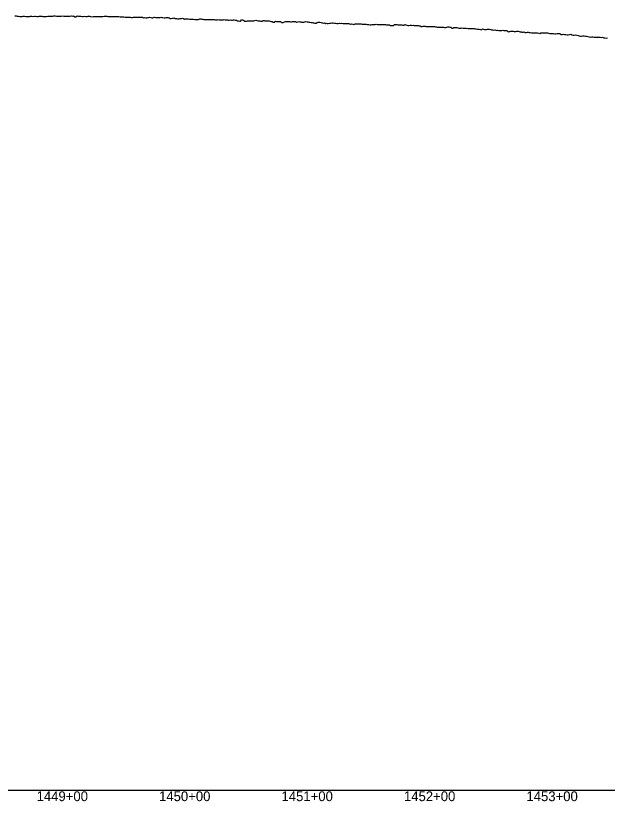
# Model space of a CAD drawing. Extents: x -3793 to 50787, y -1075 to 6138.
# Drawn here: x 32241 to 32724, y 991 to 1633 of the extents above; entities that cross this region are included whole.
import ezdxf

# ---------------------------------------------------------------- set-up
doc = ezdxf.new("R2010")
doc.units = 0
for name, color, linetype in [('RD_DDB_Profile_EX', 7, 'Continuous'), ('RD_DDB_StaTX', 7, 'Continuous'), ('RD_GPK_Profile_Cell', 7, 'Continuous')]:
    doc.layers.add(name, color=color, linetype=linetype)

msp = doc.modelspace()

# ---------------------------------------------------------------- linework, layer by layer
at = {"layer": 'RD_DDB_Profile_EX'}
for points in [[(32240.641397, 1632.72574), (32241.599053, 1632.53108), (32242.558609, 1632.480035), (32243.518571, 1632.288225), (32244.677049, 1632.131755), (32245.636323, 1631.98429), (32246.597516, 1631.98092), (32247.560636, 1632.266615), (32248.525687, 1632.26352), (32249.66571, 1632.157575), (32250.629589, 1632.106235), (32251.595418, 1632.15152), (32252.563204, 1632.196895), (32253.531405, 1632.34229), (32254.656743, 1632.439955), (32255.624286, 1632.194595), (32256.593804, 1632.24002), (32257.565305, 1632.28554), (32258.538795, 1632.136565), (32259.644937, 1632.129925), (32260.607504, 1632.224305), (32261.581846, 1632.27013), (32262.558202, 1632.21836), (32263.536578, 1632.21538), (32264.62576, 1632.213695), (32265.601917, 1632.16186), (32266.58011, 1632.1589), (32267.560345, 1632.254005), (32268.542628, 1632.300225), (32269.613406, 1632.303745), (32270.59455, 1632.300535), (32271.577764, 1632.346555), (32272.563053, 1632.58983), (32273.550424, 1632.537575), (32274.603564, 1632.285965), (32275.588701, 1632.283135), (32276.575938, 1632.32973), (32277.565279, 1632.32694), (32278.556732, 1632.373685), (32279.590678, 1632.520245), (32280.581013, 1632.36863), (32281.573481, 1632.4155), (32282.568089, 1632.46247), (32283.564845, 1632.40992), (32284.577491, 1632.30854), (32285.574884, 1632.30873), (32286.571559, 1632.554935), (32287.569303, 1632.458675), (32288.562945, 1632.51533), (32289.587271, 1631.920555), (32290.584363, 1631.92794), (32291.576172, 1632.57517), (32292.565584, 1632.479285), (32293.550939, 1632.436), (32294.608558, 1632.3379), (32295.597275, 1632.19639), (32296.580765, 1632.19959), (32297.561347, 1632.30374), (32298.538989, 1632.062265), (32299.632567, 1632.125265), (32300.610129, 1632.27509), (32301.585338, 1632.32722), (32302.557671, 1631.94539), (32303.527095, 1631.900735), (32304.653631, 1632.1362), (32305.622926, 1632.04265), (32306.590464, 1632.04886), (32307.554013, 1632.100185), (32308.515256, 1632.00712), (32309.674601, 1631.99166), (32310.635665, 1631.99425), (32311.594992, 1632.094865), (32312.550373, 1632.14506), (32313.501875, 1632.292595), (32314.695477, 1632.247825), (32315.648348, 1632.345095), (32316.599501, 1632.15975), (32317.54675, 1632.02013), (32318.490162, 1632.07229), (32319.716259, 1632.08406), (32320.662596, 1632.089215), (32321.603991, 1632.044865), (32322.543145, 1632.1414), (32323.478504, 1632.09958)], [(32323.478504, 1632.09958), (32324.412152, 1631.961905), (32324.736948, 1631.956355), (32325.675149, 1632.054825), (32326.608462, 1631.82448), (32327.539055, 1631.73703), (32328.4669, 1631.73995), (32329.392548, 1631.6965), (32329.757545, 1631.697665), (32330.687647, 1631.610995), (32331.612914, 1631.66024), (32332.535491, 1631.62003), (32333.455348, 1631.531045), (32334.370483, 1631.44536), (32334.780657, 1631.43447), (32335.70009, 1631.39174), (32336.617881, 1631.397865), (32337.531943, 1631.446665), (32338.44385, 1631.586595), (32339.356138, 1631.541125), (32339.795882, 1631.546965), (32340.709373, 1631.45892), (32341.62017, 1631.50461), (32342.530857, 1631.59583), (32343.441434, 1631.59598), (32344.349365, 1631.59894), (32344.80337, 1631.60953), (32345.712441, 1631.06436), (32346.621402, 1631.15543), (32347.530253, 1631.0193), (32348.437476, 1630.977695), (32349.345081, 1631.340945), (32349.808317, 1631.319455), (32350.715536, 1631.41032), (32351.622643, 1631.319775), (32352.529147, 1631.05115), (32353.435006, 1631.006035), (32354.340755, 1631.549685), (32354.813307, 1631.57488), (32355.718655, 1631.30349), (32356.624429, 1631.21656), (32357.528526, 1631.26194), (32358.432512, 1631.35252), (32359.336388, 1631.39789), (32359.818339, 1631.41902), (32360.723372, 1631.287275), (32361.625689, 1631.24236), (32362.527896, 1630.971915), (32363.429992, 1631.01723), (32364.329423, 1631.156445), (32364.826026, 1631.153625), (32365.726548, 1631.19884), (32366.626959, 1631.018975), (32367.527258, 1630.47905), (32368.427447, 1630.569305), (32369.324963, 1630.61883), (32369.831153, 1630.65184), (32370.729751, 1630.92161), (32371.628237, 1630.427745), (32372.526612, 1630.33818), (32373.423343, 1630.298555), (32374.32046, 1630.298825), (32374.836325, 1630.28635), (32375.732981, 1630.331435), (32376.629525, 1630.42134), (32377.525459, 1630.69491), (32378.420742, 1630.33704), (32379.315913, 1630.02398), (32379.841543, 1630.04301), (32380.736239, 1630.088025), (32381.631363, 1630.13829), (32382.524794, 1630.093905), (32383.418113, 1630.00486), (32384.311321, 1629.871165), (32384.846807, 1629.869315), (32385.74111, 1629.83057), (32386.632671, 1629.87544), (32387.52412, 1629.608325), (32388.415458, 1629.69777), (32389.304102, 1629.61478), (32389.854754, 1629.618585), (32390.744428, 1629.66337), (32391.633989, 1630.108395), (32392.523438, 1630.06421), (32393.411231, 1629.98099), (32394.299412, 1629.80364), (32394.860119, 1629.7624), (32395.747774, 1629.49644), (32396.63586, 1629.502285), (32397.522244, 1629.546895), (32398.408516, 1629.591505), (32399.292088, 1629.55296), (32399.868176, 1629.54517), (32400.743883, 1629.5454), (32401.62835, 1629.501475), (32402.512213, 1629.551365), (32403.395409, 1629.595815), (32404.278493, 1629.28701), (32404.864792, 1629.27336), (32405.748917, 1629.27922), (32406.630275, 1629.676065)], [(32406.630275, 1629.676065), (32407.511521, 1629.45605), (32408.392654, 1629.456335), (32409.271092, 1629.329955), (32409.872991, 1629.267505), (32410.75238, 1629.22381), (32411.631656, 1629.53178), (32412.510327, 1629.49274), (32413.388329, 1629.44909), (32414.266219, 1629.229865), (32414.878587, 1629.16596), (32415.757482, 1629.170615), (32416.633605, 1629.34605), (32417.509615, 1629.214885), (32418.383971, 1629.21947), (32419.258707, 1629.35092), (32419.886901, 1629.297385), (32420.761011, 1629.079105), (32421.635566, 1628.952395), (32422.5084, 1628.647155), (32423.38112, 1628.560125), (32424.253728, 1628.25495), (32424.892606, 1628.252395), (32425.766184, 1629.38955), (32426.636982, 1629.389745), (32427.507667, 1629.128755), (32428.376695, 1628.219875), (32429.246104, 1628.30709), (32429.901037, 1628.23871), (32430.76978, 1628.542935), (32431.638968, 1628.63384), (32432.50643, 1628.590675), (32433.37378, 1628.590885), (32434.238422, 1628.59498), (32434.909528, 1628.571235), (32435.775024, 1628.57143), (32436.640408, 1628.74468), (32437.505182, 1629.05079), (32438.369286, 1628.83494), (32439.233276, 1628.662315), (32439.915407, 1628.610555), (32440.77869, 1628.481265), (32441.642418, 1628.35547), (32442.504418, 1628.269465), (32443.366304, 1628.82987), (32444.225477, 1628.70381), (32444.924019, 1628.601315), (32445.784008, 1628.515455), (32446.643882, 1628.60156), (32447.503147, 1628.64688), (32448.364846, 1628.470425), (32449.228057, 1628.166525), (32449.921942, 1628.106275), (32450.781227, 1628.01787), (32451.641964, 1627.537935), (32452.506374, 1627.53503), (32453.372825, 1628.22486), (32454.244002, 1628.04693), (32454.906101, 1628.062185), (32455.771721, 1628.016345), (32456.63941, 1628.10078), (32457.50969, 1628.09586), (32458.38264, 1627.090185), (32459.257685, 1627.08657), (32459.892586, 1627.0704), (32460.761915, 1627.71931), (32461.636181, 1627.97936), (32462.51257, 1628.064655), (32463.391089, 1628.062365), (32464.274542, 1627.8816), (32464.875798, 1627.889555), (32465.753546, 1627.622835), (32466.633452, 1627.61991), (32467.516065, 1627.879), (32468.401468, 1628.00911), (32469.289059, 1628.00665), (32469.86142, 1627.962485), (32470.743137, 1627.425835), (32471.630014, 1627.64525), (32472.51911, 1627.86521), (32473.412168, 1627.81614), (32474.306913, 1627.59064), (32474.843599, 1627.576175), (32475.734217, 1627.48446), (32476.617492, 1627.56888), (32477.513837, 1627.611335), (32478.412464, 1627.87841), (32479.313381, 1627.60665), (32479.819257, 1627.592895), (32480.714121, 1627.45325), (32481.614398, 1627.45087), (32482.516998, 1627.31301), (32483.423735, 1627.081325), (32484.332252, 1627.033115), (32484.800228, 1627.03481), (32485.704532, 1626.62358), (32486.610523, 1626.61637), (32487.520827, 1627.25048), (32488.433521, 1627.43021), (32489.351743, 1627.425145), (32489.780549, 1627.374795)], [(32489.780549, 1627.374795), (32490.692663, 1627.28152), (32491.607204, 1626.95891), (32492.524776, 1626.770355), (32493.445496, 1626.85979), (32494.36868, 1626.488795), (32494.763522, 1626.50606), (32495.682406, 1626.45673), (32496.603059, 1626.449935), (32497.52824, 1626.770645), (32498.455931, 1626.76776), (32499.389426, 1626.808275), (32499.74253, 1626.7705), (32500.669737, 1626.81485), (32501.600222, 1626.721935), (32502.529942, 1626.677975), (32503.456829, 1626.355905), (32504.38419, 1626.35606), (32504.748553, 1626.360915), (32505.67765, 1626.64167), (32506.603902, 1626.45956), (32507.527324, 1626.508655), (32508.447927, 1626.46548), (32509.365725, 1626.42244), (32509.76833, 1626.395475), (32510.687673, 1626.395605), (32511.607593, 1626.352255), (32512.524698, 1626.354855), (32513.438999, 1626.357445), (32514.350511, 1625.81193), (32514.784729, 1625.8092), (32515.699772, 1625.99485), (32516.61201, 1625.770415), (32517.522063, 1625.67959), (32518.430044, 1626.092), (32519.335251, 1626.185635), (32519.801175, 1626.168355), (32520.709841, 1626.12561), (32521.615716, 1626.037815), (32522.518815, 1625.9954), (32523.419149, 1626.043205), (32524.319946, 1625.81813), (32524.817669, 1625.829805), (32525.719938, 1625.83299), (32526.619433, 1625.791305), (32527.516166, 1625.83934), (32528.410151, 1625.618855), (32529.3014, 1625.488365), (32529.837532, 1625.479825), (32530.732072, 1625.3943), (32531.62316, 1625.34994), (32532.51351, 1625.620575), (32533.401126, 1625.66833), (32534.286023, 1625.671595), (32534.854102, 1625.673695), (32535.742215, 1625.765435), (32536.627594, 1625.68024), (32537.510844, 1625.59209), (32538.392074, 1625.595485), (32539.270599, 1625.510825), (32539.870719, 1625.48311), (32540.752387, 1625.4863), (32541.631337, 1625.44564), (32542.507581, 1625.492655), (32543.38113, 1625.539525), (32544.255131, 1625.233765), (32544.887385, 1625.191925), (32545.762589, 1625.238615), (32546.63509, 1625.285165), (32547.504901, 1624.592885), (32548.372035, 1624.640285), (32549.236502, 1624.687535), (32549.907334, 1624.63667), (32550.774775, 1625.41761), (32551.638853, 1625.460915), (32552.502213, 1625.50611), (32553.362911, 1625.29279), (32554.22096, 1625.16612), (32554.924077, 1625.196415), (32555.785023, 1625.19921), (32556.642627, 1625.285095), (32557.500095, 1625.070885), (32558.357428, 1625.113905), (32559.214626, 1625.41409), (32559.93125, 1625.337025), (32560.789487, 1624.911355), (32561.644373, 1624.78327), (32562.499122, 1624.61247), (32563.353736, 1625.039915), (32564.208214, 1624.86912), (32564.938506, 1624.84924), (32565.794001, 1624.93672), (32566.646136, 1624.681235), (32567.498134, 1624.68136), (32568.349997, 1624.80927), (32569.201723, 1624.7668), (32569.945845, 1624.739025), (32570.798565, 1624.528855), (32571.647917, 1624.52898), (32572.497131, 1624.01963), (32573.346209, 1623.93489)], [(32573.346209, 1623.93489), (32574.195151, 1624.104865), (32574.953269, 1624.06202), (32575.803182, 1624.1071), (32576.649716, 1623.93796), (32577.496113, 1623.93811), (32578.342373, 1623.980575), (32579.188496, 1623.896105), (32579.96078, 1623.883365), (32580.80785, 1623.928445), (32581.651533, 1624.01294), (32582.486649, 1623.970875), (32583.330072, 1623.928845), (32584.173357, 1623.760325), (32584.959924, 1623.73953), (32585.804144, 1623.49022), (32586.644955, 1623.448355), (32587.485628, 1623.23838), (32588.326164, 1623.280595), (32589.166562, 1623.44887), (32589.967642, 1623.427975), (32590.806956, 1623.38618), (32591.646839, 1623.18), (32592.484591, 1623.222065), (32593.322204, 1623.389765), (32594.15968, 1623.599315), (32594.975452, 1623.52845), (32595.811813, 1623.444955), (32596.648744, 1623.280445), (32597.483537, 1622.48761), (32598.318193, 1622.48781), (32599.152709, 1623.030485), (32599.983356, 1622.96689), (32600.816726, 1622.96702), (32601.650668, 1622.96961), (32602.482467, 1622.761815), (32603.314128, 1622.55405), (32604.145649, 1622.55422), (32604.991356, 1622.515095), (32605.821698, 1622.722775), (32606.652613, 1622.683935), (32607.481381, 1622.642635), (32608.310009, 1622.642775), (32609.144855, 1622.38838), (32609.992791, 1622.44269), (32610.820647, 1622.397915), (32611.650983, 1622.353005), (32612.484408, 1622.346055), (32613.321071, 1622.30086), (32614.160257, 1622.297395), (32614.977258, 1622.21915), (32615.811265, 1622.258145), (32616.647071, 1622.12638), (32617.487534, 1621.871025), (32618.330572, 1621.86761), (32619.179556, 1621.8183), (32619.957636, 1621.767215), (32620.799389, 1621.42612), (32621.64376, 1621.29555), (32622.491392, 1621.88203), (32623.342441, 1621.70903), (32624.196154, 1621.4929), (32624.94084, 1621.444005), (32625.787025, 1621.394975), (32626.639531, 1621.733615), (32627.494746, 1621.730965), (32628.354778, 1621.63962), (32629.216907, 1621.37878), (32629.919683, 1621.31821), (32630.77642, 1621.05751), (32631.635116, 1621.051205), (32632.498882, 1621.09135), (32633.356817, 1620.828525), (32634.229857, 1620.777975), (32634.888915, 1620.800835), (32635.754342, 1620.710145), (32636.622626, 1620.7062), (32637.494452, 1620.74172), (32638.370024, 1620.737805), (32639.248506, 1620.821515), (32639.869797, 1620.712185), (32640.742738, 1620.62202), (32641.617739, 1620.52858), (32642.498136, 1620.56982), (32643.381511, 1619.596125), (32644.271748, 1619.808475), (32644.845816, 1619.851785), (32645.728157, 1620.0687), (32646.613532, 1620.153205), (32647.50267, 1620.144695), (32648.39579, 1619.872825), (32649.292002, 1619.86819), (32649.824987, 1619.801675), (32650.712915, 1619.973325), (32651.60821, 1620.05971), (32652.506657, 1619.83165), (32653.410696, 1619.643625), (32654.317196, 1619.4588), (32654.798922, 1619.38877), (32655.699643, 1619.385615), (32656.602632, 1619.560725)], [(32656.602632, 1619.560725), (32657.510799, 1619.01605), (32658.421269, 1619.012205), (32659.335023, 1619.28175), (32659.780647, 1619.265685), (32660.688546, 1618.98898), (32661.600753, 1618.89798), (32662.513546, 1618.80286), (32663.429683, 1618.798925), (32664.349184, 1618.703275), (32664.766249, 1618.72214), (32665.682624, 1618.7682), (32666.597799, 1618.809665), (32667.507193, 1618.667335), (32668.429202, 1618.34028), (32669.350236, 1618.202405), (32670.277311, 1618.79675), (32671.207857, 1618.69989), (32672.141891, 1618.787925), (32672.526081, 1618.75631), (32673.488844, 1618.804665), (32674.636132, 1618.74985), (32675.598194, 1618.649645), (32676.562093, 1618.500985), (32677.527414, 1618.211645), (32678.494024, 1618.11074), (32679.627525, 1618.187335), (32680.593026, 1618.231865), (32681.560948, 1617.990135), (32682.529188, 1617.98608), (32683.499295, 1618.175945), (32684.618755, 1618.11385), (32685.587757, 1618.110225), (32686.559212, 1617.333375), (32687.530989, 1617.328985), (32688.504658, 1617.66521), (32689.609816, 1617.45654), (32690.583969, 1617.31067), (32691.557439, 1617.11163), (32692.532819, 1617.05858), (32693.510115, 1617.24963), (32694.603326, 1617.530565), (32695.578512, 1617.18507), (32696.555627, 1616.88782), (32697.534679, 1616.785895), (32698.514203, 1616.982025), (32699.59407, 1616.728575), (32700.572945, 1616.57746), (32701.553776, 1616.37693), (32702.536122, 1616.082495), (32703.51984, 1616.12709), (32704.584632, 1616.21504), (32705.567267, 1616.26023), (32706.552482, 1616.1127), (32707.538036, 1616.00992), (32708.525579, 1615.758875), (32709.575006, 1615.604645), (32710.558128, 1615.29304), (32711.538183, 1615.38221), (32712.532788, 1615.516615), (32713.666404, 1615.273595), (32714.545643, 1615.11175), (32715.549194, 1615.17469), (32716.541819, 1615.33143), (32717.527251, 1615.245385), (32718.502981, 1615.06242), (32719.603963, 1615.015775), (32720.584601, 1615.172565), (32721.545248, 1614.60048), (32722.508756, 1614.6139), (32723.463069, 1614.483775), (32724.649279, 1614.62718)]]:
    msp.add_lwpolyline(points, dxfattribs=at)
at = {"layer": 'RD_GPK_Profile_Cell'}
msp.add_line((1000, 1000), (46600, 1000), dxfattribs=at)

# ---------------------------------------------------------------- texts
at = {"layer": 'RD_DDB_StaTX'}
for s, p in [('1449+00', (32258.415471, 991)), ('1450+00', (32358.415471, 991)), ('1451+00', (32458.415471, 991)), ('1452+00', (32558.415471, 991)), ('1453+00', (32658.415471, 991))]:
    msp.add_text(s, height=8, dxfattribs=at).set_placement(p)

doc.saveas('drawing.dxf')
